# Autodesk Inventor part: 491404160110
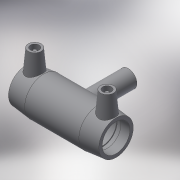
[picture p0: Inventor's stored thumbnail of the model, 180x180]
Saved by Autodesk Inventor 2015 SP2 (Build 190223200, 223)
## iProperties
Created: 2017-06
Part Number: 491404160110
Material: Generic
Description: PLASSON REDUCING TEE 160x110x160
Document SubType Name: Modeling
Designer: KIM
Mass: 57.3761 g
Surface Area: 241.06 cm^2
Volume: 57.3761 cm^3
Density: 1 g/cm^3
Appearance: Default
Author: KIM
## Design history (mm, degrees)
derived "491404.ipt"
feature "Solid1::491404.ipt"
tag "TaggingFeature1"
body "Solid1"
other parameters: "d2" = 208, "d3" = 86, "d4" = 88, "d5" = 187.2, "d6" = 152, "d8" = 168 deg, "d10" = 34.4, "d11" = 11.46667, "d14" = 17.6296, "d17" = 144, "d19" = 3.52592, "d20" = 168 deg, "d22" = 193.44, "d23" = 208, "d25" = 135 deg, "d26" = 308, "d29" = 106, "d30" = 15, "d31" = 176, "d34" = 5 deg, "d35" = 15, "d39" = 5 deg, "d41" = 4, "d42" = 14, "d43" = 0, "d45" = 4, "d46" = 6, "d47" = 0, "d48" = -193, "d51" = 0, "d52" = 88, "d54" = 0, "d55" = 187.2, "d56" = 208, "d57" = 154, "d58" = 135 deg, "d59" = 86, "d60" = 86, "d61" = 135 deg, "d62" = 193, "d72" = 200.2, "d73" = 100.1, "d74" = -193, "d75" = 115.5, "d77" = 0, "d78" = 88, "d80" = 0, "d82" = 89, "d83" = 0, "d84" = 3, "d85" = 0, "d86" = 28.66667, "d87" = 189.5712, "d88" = 11.46667, "d89" = 3, "d90" = 0, "L_1" = 86, "D_" = 208, "A_" = 106, "d_2" = 12, "H_" = 193
